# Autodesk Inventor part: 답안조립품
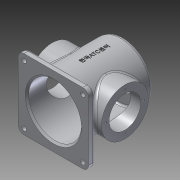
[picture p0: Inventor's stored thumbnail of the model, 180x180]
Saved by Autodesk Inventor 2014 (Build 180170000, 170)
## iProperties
Created: 2015-10
Part Number: 답안조립품
Material: 알루미늄 6061
Document SubType Name: Modeling
Designer: aapexcom
Density: 2.71 g/cm^3
Appearance: 알루미늄 - 평지
Mass: 987.646 g
Surface Area: 1042.56 cm^2
Volume: 364.445 cm^3
Author: aapexcom
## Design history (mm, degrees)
sketch "스케치1"
  geometry: L1 (0, 0)-(120, 0); L2 (120, 0)-(120, 120); L3 (120, 120)-(0, 120); L4 (0, 120)-(0, 0); 4 further points
  constraints: 8 end point, 2 midpoint, 2 parallel, 1 horizontal, 1 horizontal alignment, 1 perpendicular, 1 vertical alignment
  dimensions: "d0" = 120 distance of L2.end L3.end; "d1" = 120 distance of L1.end L2.end; "d2" = 10 distance from line of L4 point (10, 110); "d3" = 10 distance from line of L3 point (10, 110)
extrude "돌출1" new body sketch "스케치1" distance "d6" = 10; taper "d7" = 0 deg
sketch "스케치2"
  geometry: C1 r 50 at (-60, -60); 1 further point
  constraints: 1 centre point, 1 coincident
  dimensions: "d8" = 100 diameter of C1
extrude "돌출2" join sketch "스케치2" distance "d9" = 110; taper "d10" = 0 deg
hole "구멍1" sketch "스케치1" diameter "d11" = 8; stored, may be unused: countersink angle "d15" = 90 deg, drill point angle "d17" = 118 deg; dims "d12" = 6, "d13" = 4, "d14" = 2, "d16" = 8
sketch "스케치3"
  geometry: C1 r 50 at (0, 0) reference; C2 r 40 at (0, 0); 1 further point
  constraints: 1 centre point, 1 coincident
  dimensions: "d24" = 80 diameter of C2
extrude "돌출3" join sketch "스케치3" distance "d25" = 5; taper "d26" = 0 deg
hole "구멍2" sketch "스케치1" diameter "d27" = 54; stored, may be unused: countersink angle "d31" = 90 deg, drill point angle "d33" = 118 deg; dims "d28" = 6, "d29" = 90, "d30" = 112, "d32" = 8
sketch "스케치4"
  geometry: L1 (0, 0)-(0, 35.447); L2 (0, 0)-(-22.981, 22.981); C1 r 40 at (0, 0) reference; 2 further points
  constraints: 4 end point, 1 coincident, 1 vertical
  dimensions: "d34" = 32.5 distance of L1.start L2.end; "d35" = 45 deg angle of L1 L2
hole "구멍3" sketch "스케치4" at (-22.981, 22.981) diameter "d36" = 3.242; stored, may be unused: countersink angle "d40" = 90 deg, drill point angle "d42" = 118 deg; dims "d37" = 8, "d38" = 90, "d39" = 112, "d41" = 10
node "작업 평면2"
  node "작업 평면1"
sketch "스케치5"
  geometry: L1 (0, 0)-(120, 0) reference; C1 r 40 at (60, 60); 1 further point
  constraints: 1 centre point, 1 midpoint, 1 vertical alignment
  dimensions: "d47" = 60 distance from line of C1.centre L1; "d48" = 80 diameter of C1
extrude "돌출4" join sketch "스케치5" stored distance "d49" = 5; taper "d50" = 0 deg
sketch "스케치6"
  geometry: L1 (0, 0)-(0, 32.5); C1 r 40 at (0, 0) reference; 2 further points
  constraints: 2 end point, 1 coincident, 1 vertical
  dimensions: "d79" = 32.5 distance of L1.start L1.end
hole "구멍4" sketch "스케치6" at (0, 32.5) diameter "d53" = 3.242; stored, may be unused: countersink angle "d57" = 90 deg, drill point angle "d59" = 118 deg; dims "d54" = 8, "d55" = 90, "d56" = 112, "d58" = 10
sketch "스케치7"
  geometry: C1 r 40 at (0, 0) reference; 2 further points
  constraints: 1 coincident
hole "구멍5" sketch "스케치7" at (0, 0) diameter "d63" = 54; stored, may be unused: countersink angle "d67" = 90 deg, drill point angle "d69" = 118 deg; dims "d64" = 8, "d65" = 90, "d66" = 112, "d68" = 10
fillet "모깎기1" dims "d70" = 10
fillet "모깎기2" dims "d71" = 5
fillet "모깎기3" dims "d72" = 3
chamfer "모따기1" distance "d73" = 3; stored, may be unused: second distance "d74" = 2, angle "d75" = 45 deg
node "작업 평면3"
sketch "스케치8"
  geometry: L1 (-50, -10)-(50, -10) reference; 4 further points
  constraints: 2 midpoint, 1 vertical alignment, 1 other
  dimensions: "d76" = 70 distance from line of L1 point (0, 60)
feature "엠보싱1" sketch "스케치8" dims "d0" = 120, "d1" = 120, "d2" = 10, "d3" = 10, "d77" = 0.5, "d78" = 0
node "솔리드1"
pattern_linear "직사각형 패턴1" dims "d20" = 100
pattern_circular "원형 패턴1" dims angle "d44" = 360 deg
pattern_circular "원형 패턴2" dims angle "d61" = 360 deg
mirror "대칭1"
other parameters: "d46" = 62
